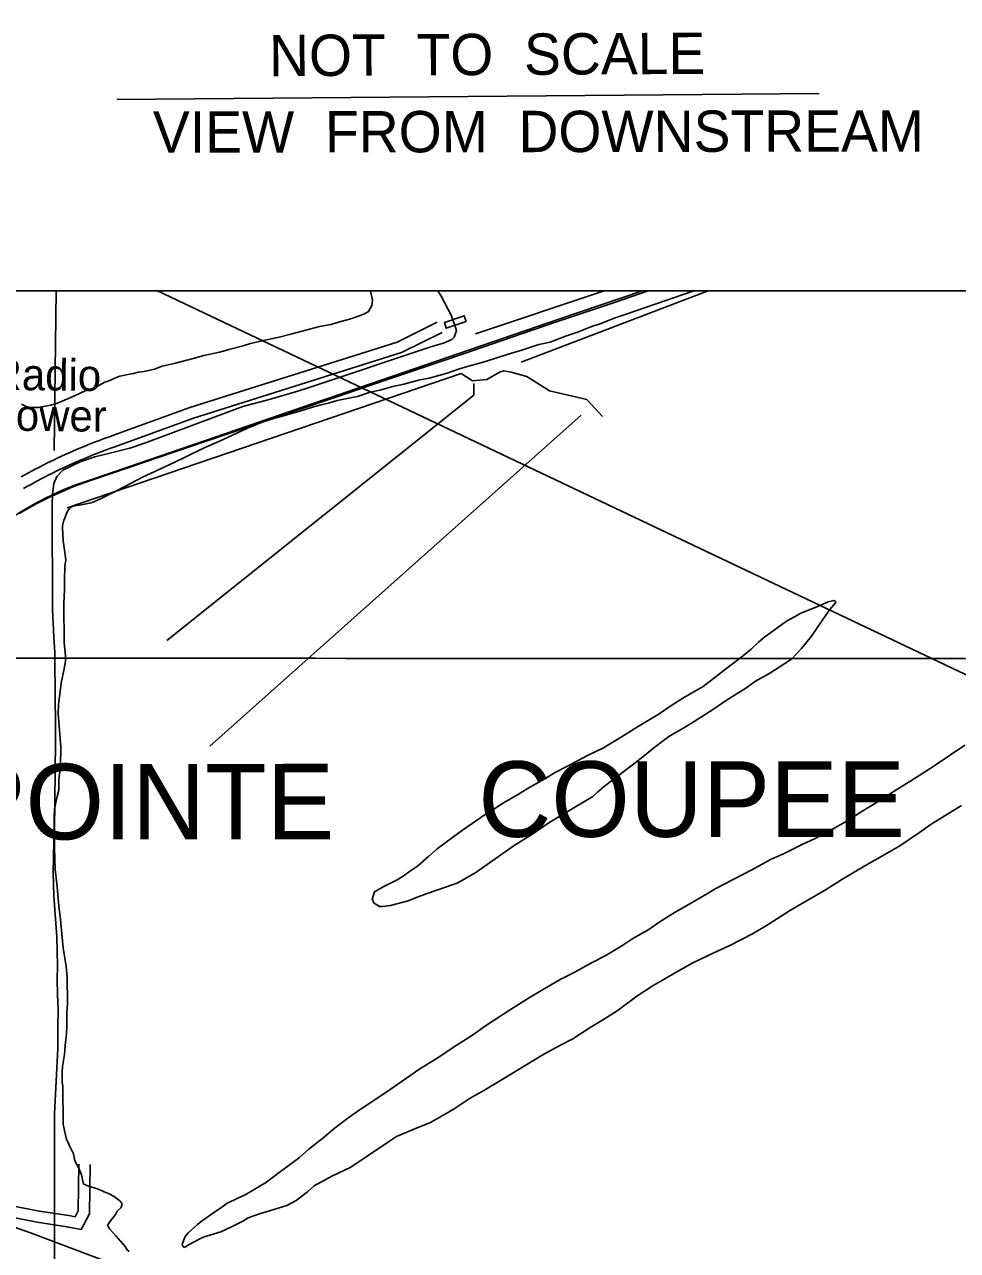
# Model space of a CAD drawing. Extents: x 3250478 to 3288318, y 788638 to 816472.
# Drawn here: x 3260258 to 3262729, y 804575 to 807821 of the extents above; entities that cross this region are included whole.
import ezdxf

# ---------------------------------------------------------------- set-up
doc = ezdxf.new("R2010")
doc.units = 0
for name, color, linetype in [('V-ANNO-SYMB', 7, 'Continuous'), ('V-BRDG-OTLN', 7, 'Continuous'), ('V-GRID-MAJR', 7, 'Continuous'), ('V-RAIL-TRAK', 7, 'Continuous'), ('V-ROAD-CNTR', 7, 'Continuous'), ('V-SITE-VEGE', 7, 'Continuous'), ('V-TOPO-GNAM-IDEN', 7, 'Continuous'), ('V-TOPO-SHOR', 7, 'Continuous'), ('V-TOPO-TOWR-IDEN', 7, 'Continuous'), ('V-UTIL-LINE', 7, 'Continuous')]:
    doc.layers.add(name, color=color, linetype=linetype)

msp = doc.modelspace()

# ---------------------------------------------------------------- linework, layer by layer
at = {"layer": 'V-ANNO-SYMB'}
msp.add_line((3260502.831450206, 807622.115767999), (3262361.8721130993, 807637.7973938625), dxfattribs=at)
msp.add_lwpolyline([(3254798.2985432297, 807115.6238858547), (3267896.0068573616, 807115.6238858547), (3267896.0068573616, 812138.0773467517), (3254798.2985432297, 812138.0773467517)], close=True, dxfattribs=at)
at = {"layer": 'V-BRDG-OTLN'}
msp.add_lwpolyline([(3261427.6410000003, 807034.461), (3261374.363, 807016.748), (3261370.166, 807031.408), (3261422.515, 807049.817)], close=True, dxfattribs=at)
at = {"layer": 'V-GRID-MAJR'}
msp.add_spline([(3254645.228, 806146.921), (3259882.848, 806143.493), (3265120.469, 806140.826), (3270358.09, 806138.922), (3275595.711, 806137.779), (3280833.333, 806137.398), (3286070.954, 806137.779), (3286070.955, 806137.779)], degree=3, dxfattribs=at)
at = {"layer": 'V-RAIL-TRAK'}
msp.add_lwpolyline([(3261909.7096772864, 807115.6238858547), (3261817.673, 807084.187), (3261664.23, 807032.512), (3261548.381, 806993.116), (3261423.326, 806950.1410000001), (3261298.271, 806907.676), (3261164.52, 806862.1410000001), (3261079.87, 806833.235), (3260978.089, 806798.956), (3260861.728, 806759.304), (3260736.417, 806716.583), (3260534.64, 806648.0260000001), (3260435.67, 806614.259), (3260391.171, 806598.143), (3260370.202, 806589.701), (3260322.8910000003, 806568.216), (3260291.18, 806552.612), (3260270.72, 806541.612), (3260244.381, 806526.523)], dxfattribs=at)
at = {"layer": 'V-ROAD-CNTR'}
msp.add_line((3260610.33461615, 807115.6238858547), (3264462.056522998, 805287.2068636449), dxfattribs=at)
for points in [[(3261894.321233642, 807115.6238858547), (3261672.706617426, 807040.7238912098), (3260439.365084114, 806617.2647381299)], [(3261351.103260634, 807032.575907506), (3261244.8514731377, 806979.85401295), (3260696.09657065, 806806.533359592), (3260487.40198804, 806730.8275110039)], [(3261364.437233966, 807005.7019612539), (3261256.103450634, 806951.9480687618), (3260705.734551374, 806778.1174164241), (3260497.63196758, 806702.6255674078)], [(3260487.5219878, 806730.870510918), (3260477.313008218, 806727.2645181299), (3260467.078028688, 806723.5645255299), (3260456.871049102, 806719.7875330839), (3260446.693069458, 806715.935540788), (3260436.5450897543, 806712.0085486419), (3260426.426109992, 806708.0065566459), (3260416.335130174, 806703.9285648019), (3260406.2761502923, 806699.7765731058), (3260396.2481703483, 806695.548581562), (3260386.251190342, 806691.2465901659), (3260376.288210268, 806686.8715989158), (3260366.35723013, 806682.4226078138), (3260356.4572499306, 806677.89961686), (3260346.5932696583, 806673.3026260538), (3260336.7642893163, 806668.6326353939), (3260326.9693089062, 806663.8896448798), (3260317.210328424, 806659.07465451), (3260307.48734787, 806654.187664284), (3260297.799367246, 806649.2276742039), (3260288.1503865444, 806644.1966842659), (3260278.5384057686, 806639.0936944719), (3260268.9644249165, 806633.9197048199), (3260259.428443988, 806628.6747153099), (3260249.9334629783, 806623.357725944)], [(3260497.51196782, 806702.5825674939), (3260487.4089880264, 806699.0145746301), (3260477.3840080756, 806695.390581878), (3260467.38702807, 806691.6915892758), (3260457.41704801, 806687.917596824), (3260447.475067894, 806684.0706045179), (3260437.56208772, 806680.1506123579), (3260427.679107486, 806676.1566203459), (3260417.826127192, 806672.0886284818), (3260408.004146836, 806667.9486367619), (3260398.213166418, 806663.7346451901), (3260388.45218594, 806659.447653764), (3260378.7232053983, 806655.090662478), (3260369.029224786, 806650.65967134), (3260359.36724411, 806646.156680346), (3260349.738263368, 806641.5826894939), (3260340.143282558, 806636.9376987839), (3260330.5843016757, 806632.2207082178), (3260321.0593207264, 806627.433717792), (3260311.5713397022, 806622.5757275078), (3260302.1183586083, 806617.646737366), (3260292.704377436, 806612.64974736), (3260283.326396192, 806607.5797575), (3260273.986414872, 806602.4427677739), (3260264.685433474, 806597.235778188), (3260255.421452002, 806591.9587887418)], [(3260432.526097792, 804803.2293662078), (3260430.48710187, 804672.705627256), (3260408.5111458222, 804631.2877100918), (3260370.7942212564, 804638.087696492), (3260292.1043786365, 804649.95867275), (3260214.773533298, 804665.485641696), (3260157.635647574, 804680.07361252), (3260123.994714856, 804685.157602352), (3260056.80784923, 804711.8685489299), (3259919.699123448, 804775.07842251)], [(3260402.530157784, 804803.6973652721), (3260400.603161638, 804680.3916118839), (3260392.2771782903, 804664.697643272), (3260375.6942114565, 804667.687637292), (3260297.298368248, 804679.5146136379), (3260221.441519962, 804694.7455831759), (3260163.6016356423, 804709.511553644), (3260131.880699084, 804714.305544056), (3260068.63782557, 804739.4484937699), (3259932.259098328, 804802.3223680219)]]:
    msp.add_lwpolyline(points, dxfattribs=at)
msp.add_arc((3260689.1139284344, 805816.4442833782), 838.8610647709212, 107.3209318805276, 125.53081521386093, dxfattribs=at)
at = {"layer": 'V-SITE-VEGE'}
for p, q in [((3261174.3361716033, 807115.6238858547), (3261174.7630000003, 807114.4710000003)), ((3261174.7630000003, 807114.4710000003), (3261179.786, 807090.779)), ((3261169.053, 807060.573), (3261156.4620000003, 807054.094)), ((3261178.369, 807076.5130000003), (3261169.053, 807060.573)), ((3261179.786, 807090.779), (3261178.369, 807076.5130000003)), ((3261083.893, 807031.088), (3261069.698, 807026.1750000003)), ((3261124.926, 807042.645), (3261083.893, 807031.088)), ((3261156.4620000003, 807054.094), (3261124.926, 807042.645)), ((3260963.9050000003, 807001.2040000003), (3260932.333, 806992.9220000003)), ((3261012.835, 807014.434), (3260963.9050000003, 807001.2040000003)), ((3261039.674, 807021.0780000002), (3261012.835, 807014.4340000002)), ((3261069.698, 807026.1750000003), (3261039.674, 807021.0780000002)), ((3260837.6, 806969.6610000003), (3260802.864, 806961.3420000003)), ((3260856.526, 806976.2120000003), (3260837.6, 806969.6610000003)), ((3260899.159, 806986.204), (3260856.526, 806976.212)), ((3260932.333, 806992.9220000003), (3260899.159, 806986.204)), ((3260704.984, 806936.4610000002), (3260654.472, 806923.212)), ((3260733.39, 806944.7060000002), (3260704.984, 806936.4610000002)), ((3260774.458, 806953.0960000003), (3260733.39, 806944.7060000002)), ((3260802.864, 806961.3420000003), (3260774.458, 806953.0960000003)), ((3260559.738, 806899.951), (3260547.11, 806896.6370000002)), ((3260575.5500000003, 806901.7160000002), (3260559.738, 806899.951)), ((3260602.392, 806908.36), (3260575.5500000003, 806901.7160000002)), ((3260622.882, 806916.5130000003), (3260602.392, 806908.36)), ((3260654.472, 806923.212), (3260622.882, 806916.513)), ((3260471.375, 806873.595), (3260441.478, 806857.42)), ((3260483.984, 806878.4920000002), (3260471.375, 806873.595)), ((3260499.744, 806885.0070000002), (3260483.984, 806878.4920000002)), ((3260510.77, 806889.8850000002), (3260499.744, 806885.0070000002)), ((3260536.0470000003, 806894.925), (3260510.77, 806889.885)), ((3260547.11, 806896.6370000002), (3260536.0470000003, 806894.925)), ((3260391.038, 806837.8350000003), (3260345.347, 806818.3070000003)), ((3260419.3880000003, 806850.827), (3260391.038, 806837.8350000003)), ((3260441.478, 806857.4200000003), (3260419.3880000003, 806850.8270000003)), ((3260263.116, 806809.4390000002), (3260250.377, 806815.6260000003)), ((3260272.651, 806806.3840000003), (3260263.116, 806809.4390000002)), ((3260294.815, 806806.64), (3260272.651, 806806.3840000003)), ((3260327.986, 806813.3550000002), (3260294.815, 806806.6400000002)), ((3260345.347, 806818.307), (3260327.986, 806813.355))]:
    msp.add_line(p, q, dxfattribs=at)
for points in [[(3260384.736, 806545.135), (3260395.992, 806547.773), (3260408.5160000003, 806549.171), (3260434.787, 806554.49), (3260448.521, 806559.665), (3260464.735, 806567.376), (3260498.398, 806584.067), (3260525.823, 806598.1780000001), (3260570.686, 806622.5210000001), (3260605.619, 806637.973), (3260656.75, 806662.389), (3260685.43, 806676.514), (3260734.068, 806699.648), (3260772.7460000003, 806716.399), (3260822.64, 806739.5430000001), (3260848.823, 806752.386), (3260887.5160000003, 806767.881), (3260921.257, 806778.304), (3260953.755, 806787.456), (3260984.999, 806796.594), (3261023.737, 806808.327), (3261043.74, 806813.574), (3261066.249, 806818.85), (3261086.238, 806825.3520000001), (3261121.273, 806832.027), (3261140.037, 806836.0040000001), (3261173.759, 806847.682), (3261198.7770000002, 806852.986), (3261233.784, 806862.167), (3261262.548, 806868.77), (3261301.3000000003, 806879.25), (3261330.0810000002, 806884.599), (3261355.085, 806891.157), (3261377.58, 806897.686), (3261407.557, 806908.0650000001), (3261433.8000000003, 806915.892), (3261472.552, 806926.37), (3261501.287, 806935.482), (3261541.264, 806948.482), (3261572.509, 806957.62), (3261619.981, 806973.216), (3261649.999, 806979.831), (3261693.6950000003, 806996.6410000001), (3261722.43, 807005.751), (3261764.873, 807022.542), (3261779.86, 807027.732), (3261822.301, 807044.523), (3261851.039, 807053.633), (3262004.663, 807106.821), (3262031.351469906, 807115.6238858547)], [(3260535.4220000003, 804573.107), (3260530.363, 804576.81), (3260525.248, 804585.529), (3260499.838, 804614.076), (3260484.589, 804631.457), (3260478.205, 804641.414), (3260483.1180000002, 804650.247), (3260499.187, 804670.496), (3260504.1, 804679.333), (3260514.014, 804689.481), (3260516.449, 804695.779), (3260516.392, 804700.792), (3260511.319, 804705.75), (3260496.127, 804718.1140000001), (3260482.25, 804725.479), (3260469.6520000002, 804730.349), (3260462.0870000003, 804734.023), (3260453.2660000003, 804737.685), (3260423.058, 804747.366), (3260418.014, 804749.8150000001), (3260414.24, 804751.025), (3260408.933, 804776.046), (3260401.194, 804794.765), (3260392.23, 804810.962), (3260390.917, 804815.963), (3260388.236, 804830.981), (3260377.9590000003, 804852.18), (3260374.099, 804860.9130000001), (3260370.261, 804867.139), (3260368.936, 804873.393), (3260365.004, 804888.395), (3260360.994, 804909.6680000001), (3260359.8200000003, 805011.226), (3260358.465, 805019.987), (3260358.161, 805046.318), (3260359.2260000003, 805062.633), (3260363.879, 805094.037), (3260366.112, 805117.888), (3260369.511, 805149.275), (3260370.517, 805170.605), (3260370.114, 805205.712), (3260372.346, 805229.563), (3260371.549, 805298.523), (3260368.7090000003, 805327.333), (3260360.6210000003, 805376.145), (3260357.678, 805413.73), (3260353.484, 805451.3), (3260349.302, 805487.617), (3260343.6040000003, 805546.4890000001), (3260339.41, 805584.06), (3260337.503, 805640.468), (3260336.578, 805720.712), (3260337.554, 805744.549), (3260344.702, 805777.235), (3260349.529, 805793.593), (3260349.21, 805821.175), (3260352.6380000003, 805850.058), (3260354.653, 805892.716), (3260354.4790000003, 805907.762), (3260347.182, 805996.709), (3260348.147, 806021.801), (3260356.228, 806082.086), (3260362.163, 806110.996), (3260366.904, 806134.875), (3260366.73, 806149.922), (3260363.832, 806183.747), (3260362.644, 806286.558), (3260364.703, 806325.456), (3260364.414, 806350.532), (3260365.248, 806386.908), (3260367.568, 806403.235), (3260360.703, 806454.5700000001), (3260359.058, 806488.409), (3260358.999, 806493.425), (3260362.6040000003, 806507.259), (3260372.344, 806532.452), (3260378.5270000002, 806540.0480000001), (3260384.736, 806545.135)], [(3262748.274, 805912.841), (3262672.3710000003, 805861.805), (3262656.187, 805851.588), (3262605.157, 805818.394), (3262567.804, 805795.3910000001), (3262514.279, 805760.915), (3262478.165, 805739.179), (3262432.108, 805709.807), (3262397.218, 805690.595), (3262349.864, 805664.968), (3262318.677, 805650.812), (3262267.561, 805625.145), (3262235.1210000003, 805610.974), (3262184.031, 805582.796), (3262086.798, 805532.767), (3262068.123, 805521.2660000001), (3262013.316, 805489.284), (3261980.921, 805471.354), (3261938.595, 805444.531), (3261911.227, 805425.407), (3261868.873, 805401.089), (3261840.254, 805381.951), (3261795.419, 805355.099), (3261759.262, 805337.1240000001), (3261711.92, 805310.2440000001), (3261677.0160000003, 805292.285), (3261629.677, 805265.405), (3261597.294, 805246.2220000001), (3261545.0100000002, 805213.013), (3261479.0500000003, 805169.616), (3261444.22, 805145.388), (3261394.429, 805113.464), (3261358.343, 805089.2220000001), (3261302.312, 805054.7170000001), (3261269.974, 805031.7710000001), (3261226.438, 805001.172), (3261194.085, 804979.482), (3261146.789, 804948.84), (3261118.182, 804928.444), (3261078.406, 804897.89), (3261052.323, 804876.2710000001), (3261011.324, 804843.194), (3260986.494, 804821.589), (3260959.143, 804801.21), (3260933.029, 804782.1), (3260899.464, 804756.631), (3260879.535, 804745.115), (3260853.392, 804728.512), (3260840.926, 804722.0970000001), (3260824.714, 804714.387), (3260814.7430000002, 804709.2540000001), (3260794.7830000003, 804700.247), (3260777.375, 804687.507), (3260759.95, 804676.019), (3260747.515, 804667.096), (3260726.373, 804651.806), (3260716.428, 804644.165), (3260707.739, 804636.542), (3260692.8540000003, 804622.5750000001), (3260684.193, 804612.4450000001), (3260675.646, 804592.283), (3260676.9450000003, 804588.535), (3260680.764, 804583.562), (3260684.5100000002, 804584.861), (3260695.7090000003, 804592.514), (3260704.441, 804596.377), (3260731.866, 804610.488), (3260778.098, 804624.8150000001), (3260806.79, 804637.687), (3260836.707, 804653.0800000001)], [(3260836.707, 804653.0800000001), (3260850.398, 804662.015), (3260880.375, 804672.394), (3260906.6180000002, 804680.2220000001), (3260952.849, 804694.55), (3260977.782, 804707.376), (3261007.613, 804730.2930000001), (3261024.978, 804746.794), (3261072.3340000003, 804772.4230000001), (3261122.223, 804795.569), (3261221.762, 804863.18), (3261242.918, 804877.219), (3261297.825, 804900.425), (3261331.5330000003, 804913.354), (3261370.154, 804935.118), (3261396.311, 804950.468), (3261438.623, 804978.546), (3261474.752, 804999.0260000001), (3261527.051, 805030.979), (3261568.151, 805055.278), (3261629.167, 805092.349), (3261674.028, 805116.694), (3261710.173, 805135.92), (3261756.231, 805165.295), (3261791.092, 805187.0160000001), (3261827.1920000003, 805210.005), (3261879.418, 805248.2270000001), (3261920.488, 805275.035), (3261985.252, 805313.402), (3262027.6210000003, 805336.463), (3262083.739, 805363.4450000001), (3262126.153, 805382.745), (3262185.987, 805413.531), (3262227.086, 805437.832), (3262286.8370000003, 805476.14), (3262330.43, 805501.726), (3262376.521, 805528.5920000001), (3262423.83, 805557.978), (3262454.957, 805577.148), (3262483.607, 805593.781), (3262535.935, 805623.228), (3262575.795, 805646.259), (3262628.0500000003, 805681.975), (3262659.149, 805703.6510000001), (3262708.954, 805734.321), (3262738.828, 805753.476)]]:
    msp.add_lwpolyline(points, dxfattribs=at)
msp.add_lwpolyline([(3261649.624, 805709.545), (3261762.954, 805777.3150000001), (3261775.363, 805788.745), (3261793.9960000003, 805804.009), (3261841.221, 805840.92), (3261874.785, 805866.387), (3261899.644, 805885.482), (3261924.488, 805905.833), (3261950.6, 805924.9450000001), (3261966.757, 805937.671), (3262005.378, 805959.435), (3262031.521, 805976.039), (3262082.563, 806007.9770000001), (3262117.395, 806032.2050000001), (3262168.44, 806064.1460000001), (3262193.315, 806081.99), (3262231.936, 806103.7540000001), (3262256.838, 806119.087), (3262289.1920000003, 806140.78), (3262315.204, 806168.667), (3262342.409, 806201.585), (3262371.995, 806245.816), (3262390.498, 806272.3640000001), (3262405.34, 806290.091), (3262405.2970000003, 806293.851), (3262401.506, 806296.317), (3262386.505, 806292.381), (3262356.559, 806279.495), (3262314.116, 806262.703), (3262299.1720000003, 806253.7540000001), (3262280.482, 806243.505), (3262263.057, 806232.018), (3262236.9450000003, 806212.908), (3262218.282, 806200.1510000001), (3262200.903, 806184.904), (3262182.299, 806167.133), (3262167.397, 806154.419), (3262143.778, 806136.5920000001), (3262122.651, 806120.044), (3262082.874, 806089.492), (3262055.54, 806067.857), (3262005.7060000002, 806039.6950000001), (3261972.0840000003, 806019.241), (3261936.012, 805993.746), (3261881.208, 805961.762), (3261847.6, 805940.057), (3261791.569, 805905.5530000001), (3261750.41, 805886.267), (3261694.322, 805856.777), (3261661.91, 805840.103), (3261635.769, 805823.497), (3261592.161, 805799.167), (3261563.526, 805781.282), (3261524.9050000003, 805759.518), (3261502.506, 805744.211), (3261472.62, 805726.312), (3261455.214, 805713.569), (3261417.887, 805688.059), (3261391.775, 805668.947), (3261350.745, 805638.3790000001), (3261328.41, 805618.056), (3261298.607, 805592.633), (3261277.453, 805578.596), (3261261.2970000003, 805565.867), (3261245.095, 805556.903), (3261210.1950000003, 805538.944), (3261185.275, 805524.862), (3261179.239, 805504.726), (3261184.372, 805494.757), (3261198.2630000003, 805486.139), (3261207.041, 805486.241), (3261227.073, 805488.979), (3261244.583, 805492.944), (3261274.59, 805500.8150000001), (3261293.309, 805508.554), (3261324.523, 805520.201), (3261373.234, 805537.064), (3261405.703, 805548.725), (3261453.043, 805575.608), (3261489.114, 805601.103), (3261555.045, 805647.009), (3261598.61, 805675.099)], close=True, dxfattribs=at)
at = {"layer": 'V-TOPO-SHOR'}
for p, q in [((3261573.0972731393, 806926.6304576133), (3262068.6964173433, 807115.6238858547)), ((3260748.7843449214, 805910.0783796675), (3261731.812183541, 806786.7281550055))]:
    msp.add_line(p, q, dxfattribs=at)
for points in [[(3261353.141376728, 807115.6238858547), (3261361.2120000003, 807101.171), (3261388.6520000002, 807049.121), (3261393.12, 807035.948), (3261397.161, 807026.175), (3261402.058, 807010.242), (3261396.114, 806993.237), (3261390.169, 806987.073), (3261367.649, 806976.861), (3261339.3910000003, 806969.411), (3261004.3340000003, 806857.047), (3260976.078, 806847.897), (3260909.575, 806828.527), (3260836.697, 806809.155), (3260578.772, 806713.616), (3260537.554, 806699.1460000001), (3260487.624, 806686.371), (3260444.278, 806676.5750000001), (3260405.609, 806663.382), (3260360.146, 806641.049), (3260343.793, 806624.464), (3260336.365, 806605.336), (3260332.553, 806576.434), (3260331.503, 806549.448), (3260332.2770000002, 806271.9230000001), (3260335.924, 806198.402), (3260338.281, 806158.028), (3260338.515, 806115.317), (3260339.387, 806071.3300000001), (3260339.4080000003, 806029.893), (3260340.919, 805979.107), (3260340.522, 805923.006), (3260337.663, 805686.707), (3260335.975, 805659.082), (3260334.933, 805615.732), (3260334.528, 805576.845), (3260336.258, 805513.944), (3260340.751, 805453.598), (3260343.75, 805405.787), (3260345.255, 805367.963), (3260345.486, 805329.925), (3260345.292, 805292.951), (3260345.947, 805253.215), (3260347.88, 805211.5650000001), (3260346.625, 805170.341), (3260346.656, 805109.991)], [(3260337.0033917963, 806692.6365266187), (3260342.1027805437, 807115.6238858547)], [(3261452.285, 807001.968), (3261792.6985730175, 807115.6238858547)], [(3260370.978464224, 806541.4308251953), (3261414.3328810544, 806896.4374794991), (3261444.566544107, 806877.52920712), (3261482.3665949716, 806881.2981063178), (3261516.391149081, 806900.1876856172), (3261527.7319340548, 806903.9642819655), (3261546.6303100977, 806900.1788888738), (3261588.2058577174, 806888.82710797), (3261648.6731838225, 806851.0105632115), (3261746.9438595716, 806828.3026030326), (3261788.5095108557, 806782.9317659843)], [(3260635.468860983, 806189.8236068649), (3261448.335443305, 806839.7291562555), (3261448.3442400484, 806869.9683172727)], [(3260347.1492994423, 802471.5736652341), (3260352.3466904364, 802897.739183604), (3260352.4322918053, 803191.9973463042), (3260347.3883929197, 803293.4671541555), (3260342.3592528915, 803445.6711279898), (3260347.5094155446, 803709.4873152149), (3260347.6614317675, 804232.0492248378), (3260337.6075793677, 804551.6774223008), (3260337.7197466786, 804937.2570837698), (3260346.656, 805109.991)]]:
    msp.add_lwpolyline(points, dxfattribs=at)
at = {"layer": 'V-UTIL-LINE'}
msp.add_lwpolyline([(3254656.329, 806009.862), (3255230.555, 806065.091), (3256792.293, 806260.756), (3257444.444, 805974.433), (3258347.769, 805560.02), (3259185.365, 805043.422), (3259401.383, 804927.898), (3260274.107, 804622.1950000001), (3261329.378, 804224.2050000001)], dxfattribs=at)

# ---------------------------------------------------------------- texts
at = {"layer": 'V-ANNO-SYMB'}
for s, height, rotation, p in [('NOT  TO  SCALE', 109.48507047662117, 0.32496677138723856, (3260906.160458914, 807683.3749587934)), ('VIEW  FROM  DOWNSTREAM', 109.48507047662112, 0.09277453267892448, (3260598.4726511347, 807480.9947419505))]:
    msp.add_text(s, height=height, rotation=rotation, dxfattribs=at).set_placement(p)
at = {"layer": 'V-TOPO-GNAM-IDEN'}
for s, height, rotation, p in [('POINTE', 199.999598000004, 0.008275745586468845, (3260082.696736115, 805663.4280477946)), ('COUPEE', 199.99959800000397, 359.9943222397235, (3261459.857793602, 805670.2851788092))]:
    msp.add_text(s, height=height, rotation=rotation, dxfattribs=at).set_placement(p)
at = {"layer": 'V-TOPO-TOWR-IDEN'}
for s, height, p in [('Radio', 82.99983200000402, (3260170.925450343, 806853.5926245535)), ('Tower', 82.999998, (3260167.333088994, 806745.9903552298))]:
    msp.add_text(s, height=height, rotation=359.3568115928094, dxfattribs=at).set_placement(p)

doc.saveas('drawing.dxf')
